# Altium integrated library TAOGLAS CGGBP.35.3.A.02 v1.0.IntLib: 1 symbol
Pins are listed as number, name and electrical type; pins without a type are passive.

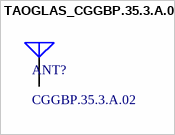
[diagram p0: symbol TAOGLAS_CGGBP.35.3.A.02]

## TAOGLAS_CGGBP.35.3.A.02
designator ANT?, comment CGGBP.35.3.A.02
35mm*35mm*3mm 4dBi+ GPS/GLONASS/Galileo/BeiDou/QZSS Ceramic Patch Antenna; ComponentLibStatus: Created; MFG: Taoglas
footprint TAOGLAS_CGGBP.35.3.A.02 (35mm*35mm*3mm 4dBi+ GPS/GLONASS/Galileo/BeiDou/QZSS Ceramic Patch Antenna)
pins: 1 RF FEED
